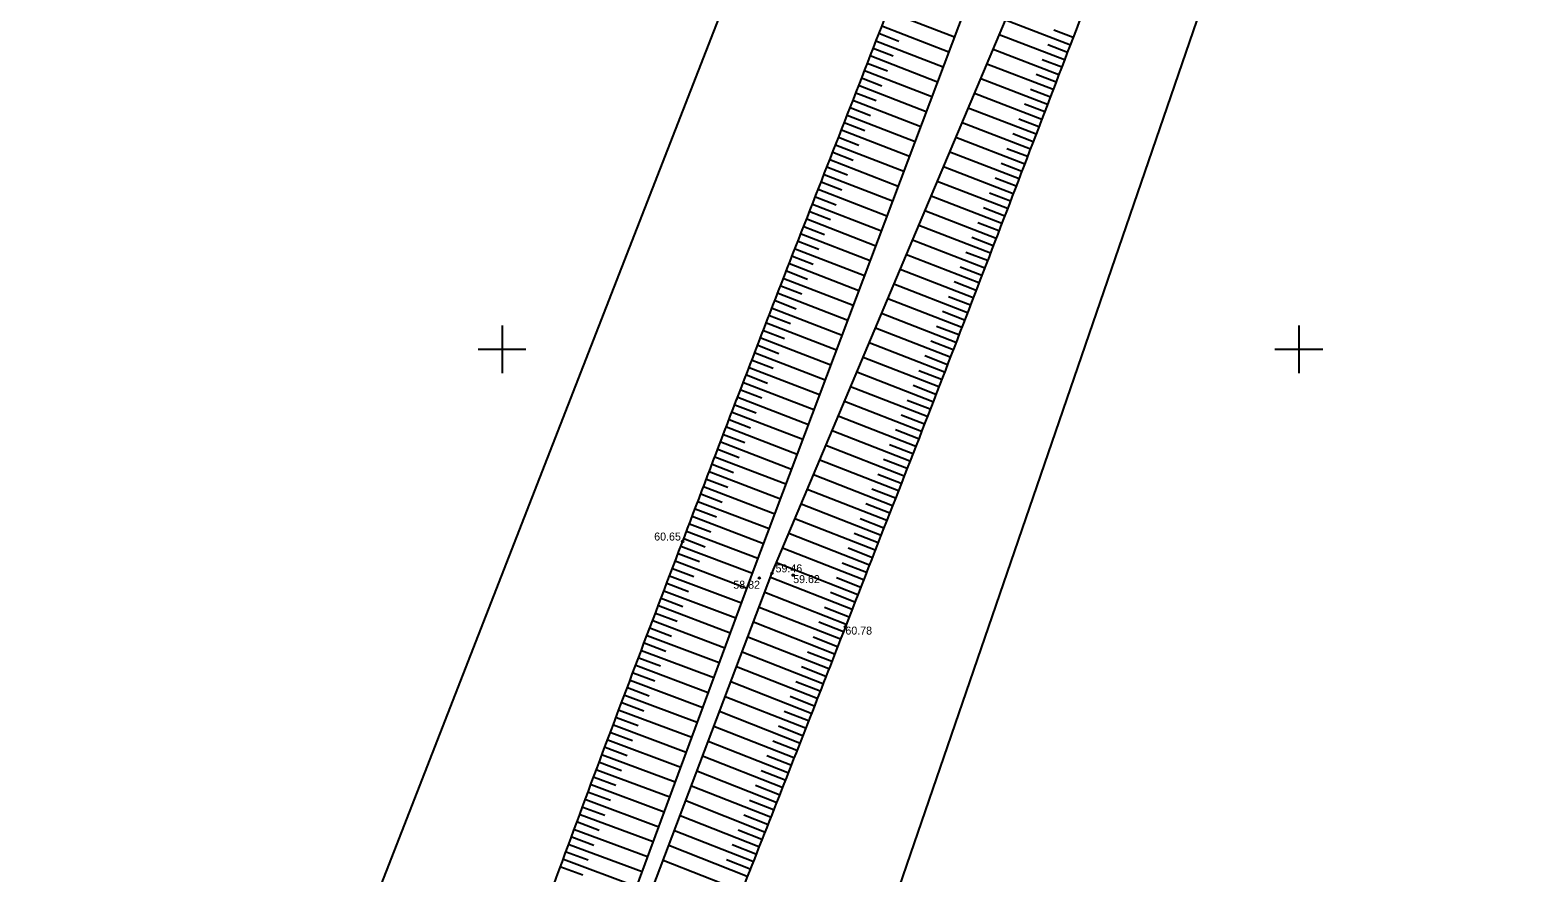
# Model space of a CAD drawing. Extents: x 616607 to 617499, y 408385 to 409695.
# Drawn here: x 617070.4 to 617165, y 408817.1 to 408870 of the extents above; entities that cross this region are included whole.
import ezdxf

# ---------------------------------------------------------------- set-up
doc = ezdxf.new("R2010")
doc.units = 0
for name, color, linetype in [('GEOD_ELEM_####_####_#', 7, 'Continuous'), ('HIDG_GRAV_####_####_#', 7, 'Continuous'), ('RAMI_UZMR_####_####_#', 7, 'Continuous'), ('RELJ_AATZ_####_TKST_#', 7, 'Continuous'), ('RELJ_ELEM_####_####_#', 7, 'Continuous'), ('RELJ_NOGA_####_####_#', 7, 'Continuous')]:
    doc.layers.add(name, color=color, linetype=linetype)

# ---------------------------------------------------------------- blocks, each defined once
blk = doc.blocks.new('PKT')
at = {"layer": 'RELJ_ELEM_####_####_#'}
blk.add_circle((0, 0), 0.05, dxfattribs=at)
blk = doc.blocks.new('KRUSTS')
at = {"layer": 'GEOD_ELEM_####_####_#'}
for p, q in [((0, 1.5), (0, 0)), ((-1.5, 0), (0, 0)), ((0, 0), (0, -1.5)), ((0, 0), (1.5, 0))]:
    blk.add_line(p, q, dxfattribs=at)

msp = doc.modelspace()

# ---------------------------------------------------------------- linework, layer by layer
at = {"layer": 'HIDG_GRAV_####_####_#'}
msp.add_lwpolyline([(616957.708, 408604.801), (616964.717, 408618.582), (616997.814, 408672.816), (617082.506, 408751.106), (617088.497, 408760.889), (617116.937, 408835.934), (617137.451, 408884.548), (617152.78, 408924.733), (617163.79, 408955.542), (617160.997, 408956.152), (617115.742, 408836.043), (617088.001, 408760.943), (617081.506, 408751.106), (616997.147, 408673.705), (616963.717, 408618.582), (616956.708, 408604.801)], dxfattribs=at)
at = {"layer": 'RAMI_UZMR_####_####_#'}
for points in [[(617191.828, 409115.62), (617145.545, 408952.8), (617072.809, 408766.141), (616965.332, 408652.076), (616939.432, 408594.661), (616924.839, 408592.467), (616706.433, 408526.081), (616666.426, 408467.691)], [(616666.426, 408467.691), (616675.529, 408457.882), (616687.228, 408463.356), (616723.888, 408465.775), (616753.554, 408507.232), (616948.282, 408568.831), (616981.528, 408608.531), (617014.563, 408672.892), (617101.571, 408748.246), (617213.472, 409074.039)]]:
    msp.add_lwpolyline(points, dxfattribs=at)
at = {"layer": 'RELJ_NOGA_####_####_#'}
for p, q in [((617124.186, 408871.235), (617128.389, 408869.609)), ((617123.825, 408870.303), (617128.036, 408868.672)), ((617135.664, 408869.103), (617131.591, 408870.661)), ((617123.405, 408869.219), (617123.406, 408869.219)), ((617123.464, 408869.37), (617127.684, 408867.736)), ((617123.586, 408869.685), (617123.587, 408869.685)), ((617123.645, 408869.837), (617124.909, 408869.347)), ((617135.306, 408868.169), (617131.203, 408869.741)), ((617135.843, 408869.57), (617134.626, 408870.035)), ((617123.044, 408868.287), (617123.044, 408868.286)), ((617123.103, 408868.438), (617127.33, 408866.798)), ((617123.225, 408868.753), (617123.226, 408868.752)), ((617123.283, 408868.904), (617124.55, 408868.413)), ((617134.949, 408867.235), (617130.814, 408868.819)), ((617135.485, 408868.636), (617134.259, 408869.105)), ((617122.682, 408867.354), (617122.682, 408867.354)), ((617122.741, 408867.506), (617126.978, 408865.862)), ((617122.863, 408867.82), (617122.864, 408867.82)), ((617122.922, 408867.972), (617124.191, 408867.479)), ((617134.591, 408866.301), (617130.425, 408867.897)), ((617135.128, 408867.702), (617133.892, 408868.175)), ((617122.321, 408866.422), (617122.321, 408866.422)), ((617122.379, 408866.573), (617126.625, 408864.926)), ((617122.501, 408866.888), (617122.502, 408866.888)), ((617122.56, 408867.039), (617123.832, 408866.546)), ((617134.233, 408865.367), (617130.036, 408866.976)), ((617134.77, 408866.768), (617133.525, 408867.245)), ((617121.959, 408865.49), (617121.959, 408865.489)), ((617122.018, 408865.641), (617126.272, 408863.991)), ((617122.14, 408865.956), (617122.141, 408865.955)), ((617122.198, 408866.107), (617123.474, 408865.612)), ((617133.875, 408864.434), (617129.647, 408866.055)), ((617134.412, 408865.834), (617133.158, 408866.315)), ((617121.597, 408864.557), (617121.598, 408864.557)), ((617121.656, 408864.709), (617125.92, 408863.055)), ((617121.778, 408865.023), (617121.779, 408865.023)), ((617121.837, 408865.175), (617123.115, 408864.679)), ((617133.517, 408863.5), (617129.259, 408865.134)), ((617134.054, 408864.9), (617132.79, 408865.385)), ((617121.236, 408863.625), (617121.236, 408863.625)), ((617121.294, 408863.776), (617125.567, 408862.119)), ((617121.416, 408864.091), (617121.417, 408864.091)), ((617121.475, 408864.242), (617122.756, 408863.746)), ((617133.158, 408862.566), (617128.87, 408864.212)), ((617133.696, 408863.967), (617132.423, 408864.455)), ((617120.874, 408862.693), (617120.874, 408862.693)), ((617120.933, 408862.844), (617125.215, 408861.183)), ((617121.055, 408863.159), (617121.056, 408863.158)), ((617121.114, 408863.31), (617122.397, 408862.812)), ((617132.8, 408861.633), (617128.481, 408863.291)), ((617132.979, 408862.1), (617131.688, 408862.595)), ((617133.338, 408863.033), (617132.056, 408863.525)), ((617120.512, 408861.76), (617120.513, 408861.76)), ((617120.571, 408861.912), (617124.862, 408860.247)), ((617120.693, 408862.226), (617120.694, 408862.226)), ((617120.752, 408862.378), (617122.038, 408861.879)), ((617132.442, 408860.699), (617128.092, 408862.37)), ((617132.621, 408861.166), (617131.321, 408861.665)), ((617120.151, 408860.828), (617120.151, 408860.828)), ((617120.209, 408860.979), (617124.509, 408859.311)), ((617120.332, 408861.294), (617120.332, 408861.294)), ((617120.39, 408861.446), (617121.679, 408860.946)), ((617132.083, 408859.766), (617127.704, 408861.449)), ((617132.262, 408860.233), (617130.953, 408860.736)), ((617119.789, 408859.896), (617119.789, 408859.896)), ((617119.848, 408860.047), (617124.157, 408858.376)), ((617119.97, 408860.362), (617119.971, 408860.361)), ((617120.029, 408860.513), (617121.32, 408860.012)), ((617131.724, 408858.832), (617127.315, 408860.527)), ((617131.903, 408859.299), (617130.585, 408859.806)), ((617119.427, 408858.963), (617119.428, 408858.963)), ((617119.486, 408859.115), (617123.804, 408857.44)), ((617119.608, 408859.43), (617119.609, 408859.429)), ((617119.667, 408859.581), (617120.961, 408859.079)), ((617131.365, 408857.899), (617126.927, 408859.607)), ((617131.545, 408858.366), (617130.217, 408858.876)), ((617119.066, 408858.031), (617119.066, 408858.031)), ((617119.124, 408858.182), (617123.452, 408856.504)), ((617119.247, 408858.497), (617119.248, 408858.497)), ((617119.305, 408858.649), (617120.602, 408858.146)), ((617131.006, 408856.966), (617126.538, 408858.686)), ((617131.185, 408857.432), (617129.849, 408857.946)), ((617118.704, 408857.099), (617118.704, 408857.099)), ((617118.763, 408857.25), (617123.099, 408855.568)), ((617118.885, 408857.565), (617118.886, 408857.565)), ((617118.944, 408857.716), (617120.243, 408857.212)), ((617130.647, 408856.033), (617126.149, 408857.764)), ((617130.826, 408856.499), (617129.481, 408857.017)), ((617118.342, 408856.166), (617118.343, 408856.166)), ((617118.401, 408856.318), (617122.746, 408854.632)), ((617118.523, 408856.633), (617118.524, 408856.632)), ((617118.582, 408856.784), (617119.884, 408856.279)), ((617130.287, 408855.099), (617125.761, 408856.844)), ((617130.467, 408855.566), (617129.113, 408856.087)), ((617117.981, 408855.234), (617117.981, 408855.234)), ((617118.04, 408855.385), (617122.395, 408853.699)), ((617118.162, 408855.7), (617118.163, 408855.7)), ((617118.22, 408855.852), (617119.525, 408855.345)), ((617129.927, 408854.166), (617125.372, 408855.922)), ((617130.107, 408854.633), (617128.745, 408855.158)), ((617117.62, 408854.302), (617117.62, 408854.301)), ((617117.679, 408854.453), (617122.042, 408852.763)), ((617117.801, 408854.768), (617117.801, 408854.767)), ((617117.859, 408854.919), (617119.167, 408854.413)), ((617129.208, 408852.3), (617124.595, 408854.08)), ((617129.568, 408853.233), (617124.983, 408855.002)), ((617129.748, 408853.7), (617128.377, 408854.229)), ((617117.259, 408853.369), (617117.259, 408853.369)), ((617117.318, 408853.52), (617121.69, 408851.829)), ((617117.439, 408853.835), (617117.44, 408853.835)), ((617117.498, 408853.987), (617118.808, 408853.479)), ((617128.848, 408851.367), (617124.206, 408853.159)), ((617129.388, 408852.767), (617128.008, 408853.299)), ((617116.898, 408852.436), (617116.898, 408852.436)), ((617116.957, 408852.588), (617121.338, 408850.893)), ((617117.079, 408852.903), (617117.079, 408852.902)), ((617117.137, 408853.054), (617118.45, 408852.546)), ((617128.487, 408850.435), (617123.818, 408852.239)), ((617129.028, 408851.834), (617127.639, 408852.37)), ((617116.538, 408851.504), (617116.538, 408851.503)), ((617116.596, 408851.655), (617120.986, 408849.959)), ((617116.718, 408851.97), (617116.719, 408851.97)), ((617116.776, 408852.121), (617118.092, 408851.612)), ((617128.127, 408849.502), (617123.429, 408851.318)), ((617128.667, 408850.901), (617127.271, 408851.441)), ((617116.177, 408850.571), (617116.178, 408850.571)), ((617116.236, 408850.722), (617120.633, 408849.023)), ((617116.357, 408851.037), (617116.358, 408851.037)), ((617116.416, 408851.189), (617117.734, 408850.679)), ((617127.766, 408848.569), (617123.041, 408850.398)), ((617128.307, 408849.968), (617126.902, 408850.511)), ((617115.817, 408849.638), (617115.817, 408849.638)), ((617115.876, 408849.789), (617120.282, 408848.09)), ((617115.997, 408850.104), (617115.998, 408850.104)), ((617116.056, 408850.256), (617117.376, 408849.746)), ((617127.405, 408847.637), (617122.652, 408849.476)), ((617127.946, 408849.036), (617126.533, 408849.582)), ((617115.336, 408848.39), (617116.661, 408847.879)), ((617115.457, 408848.705), (617115.458, 408848.705)), ((617115.516, 408848.856), (617119.929, 408847.154)), ((617115.637, 408849.171), (617115.638, 408849.171)), ((617115.696, 408849.323), (617117.019, 408848.813)), ((617127.044, 408846.704), (617122.264, 408848.557)), ((617127.585, 408848.103), (617126.164, 408848.653)), ((617114.976, 408847.457), (617116.304, 408846.946)), ((617115.098, 408847.772), (617115.098, 408847.772)), ((617115.156, 408847.923), (617119.576, 408846.219)), ((617115.277, 408848.238), (617115.278, 408848.238)), ((617126.682, 408845.772), (617121.875, 408847.635)), ((617127.224, 408847.17), (617125.794, 408847.724)), ((617114.617, 408846.523), (617115.947, 408846.012)), ((617114.738, 408846.839), (617114.739, 408846.838)), ((617114.797, 408846.99), (617119.225, 408845.285)), ((617114.918, 408847.305), (617114.919, 408847.305)), ((617126.321, 408844.839), (617121.487, 408846.715)), ((617126.863, 408846.238), (617125.425, 408846.795)), ((617114.258, 408845.59), (617115.59, 408845.079)), ((617114.379, 408845.905), (617114.38, 408845.905)), ((617114.438, 408846.057), (617118.873, 408844.351)), ((617114.559, 408846.372), (617114.56, 408846.372)), ((617125.959, 408843.907), (617121.098, 408845.794)), ((617126.502, 408845.305), (617125.055, 408845.866)), ((617113.9, 408844.656), (617115.233, 408844.144)), ((617114.021, 408844.972), (617114.021, 408844.972)), ((617114.079, 408845.123), (617118.521, 408843.418)), ((617114.2, 408845.438), (617114.201, 408845.438)), ((617125.597, 408842.975), (617120.709, 408844.874)), ((617126.14, 408844.373), (617124.686, 408844.938)), ((617113.542, 408843.723), (617114.877, 408843.211)), ((617113.663, 408844.038), (617113.663, 408844.038)), ((617113.721, 408844.19), (617118.169, 408842.484)), ((617113.842, 408844.505), (617113.842, 408844.505)), ((617125.235, 408842.043), (617120.321, 408843.954)), ((617125.778, 408843.441), (617124.316, 408844.009)), ((617113.184, 408842.789), (617114.521, 408842.277)), ((617113.305, 408843.104), (617113.305, 408843.104)), ((617113.363, 408843.256), (617117.817, 408841.548)), ((617113.484, 408843.571), (617113.484, 408843.571)), ((617124.873, 408841.111), (617119.932, 408843.032)), ((617125.416, 408842.509), (617123.946, 408843.08)), ((617112.827, 408841.855), (617114.166, 408841.343)), ((617112.947, 408842.17), (617112.947, 408842.17)), ((617113.005, 408842.322), (617117.465, 408840.615)), ((617113.126, 408842.637), (617113.127, 408842.637)), ((617124.51, 408840.179), (617119.544, 408842.112)), ((617125.054, 408841.577), (617123.576, 408842.151)), ((617112.47, 408840.921), (617113.81, 408840.409)), ((617112.59, 408841.236), (617112.59, 408841.236)), ((617112.648, 408841.388), (617117.114, 408839.682)), ((617112.769, 408841.703), (617112.77, 408841.703)), ((617124.147, 408839.247), (617119.155, 408841.191)), ((617124.691, 408840.645), (617123.206, 408841.223)), ((617112.113, 408839.986), (617113.455, 408839.475)), ((617112.234, 408840.302), (617112.234, 408840.302)), ((617112.291, 408840.454), (617116.762, 408838.749)), ((617112.412, 408840.769), (617112.413, 408840.769)), ((617123.784, 408838.315), (617118.767, 408840.271)), ((617124.328, 408839.713), (617122.835, 408840.294)), ((617111.757, 408839.052), (617113.1, 408838.541)), ((617111.877, 408839.368), (617111.878, 408839.368)), ((617111.935, 408839.519), (617116.41, 408837.813)), ((617112.055, 408839.835), (617112.056, 408839.834)), ((617123.421, 408837.384), (617118.379, 408839.35)), ((617123.966, 408838.781), (617122.464, 408839.366)), ((617111.402, 408838.117), (617112.746, 408837.606)), ((617111.522, 408838.433), (617111.522, 408838.433)), ((617111.579, 408838.585), (617116.058, 408836.881)), ((617111.7, 408838.9), (617111.7, 408838.9)), ((617123.057, 408836.452), (617117.99, 408838.43)), ((617123.602, 408837.849), (617122.093, 408838.438)), ((617111.047, 408837.182), (617112.393, 408836.672)), ((617111.167, 408837.498), (617111.167, 408837.498)), ((617111.224, 408837.65), (617115.708, 408835.949)), ((617111.344, 408837.966), (617111.345, 408837.965)), ((617122.693, 408835.521), (617117.602, 408837.511)), ((617123.239, 408836.918), (617121.723, 408837.51)), ((617110.635, 408836.096), (617110.636, 408836.095)), ((617110.692, 408836.247), (617112.041, 408835.737)), ((617110.812, 408836.563), (617110.812, 408836.563)), ((617110.869, 408836.715), (617115.361, 408835.011)), ((617110.989, 408837.031), (617110.99, 408837.03)), ((617122.329, 408834.589), (617117.214, 408836.589)), ((617122.875, 408835.986), (617121.352, 408836.582)), ((617110.281, 408835.16), (617110.282, 408835.16)), ((617110.338, 408835.312), (617111.69, 408834.801)), ((617110.458, 408835.628), (617110.458, 408835.628)), ((617110.515, 408835.78), (617115.016, 408834.076)), ((617121.964, 408833.658), (617116.836, 408835.666)), ((617122.511, 408835.055), (617120.98, 408835.653)), ((617109.927, 408834.225), (617109.928, 408834.225)), ((617109.985, 408834.377), (617111.338, 408833.865)), ((617110.104, 408834.693), (617110.104, 408834.693)), ((617110.161, 408834.845), (617114.67, 408833.141)), ((617121.6, 408832.727), (617116.481, 408834.731)), ((617122.147, 408834.124), (617120.609, 408834.726)), ((617109.574, 408833.289), (617109.575, 408833.289)), ((617109.631, 408833.441), (617110.987, 408832.93)), ((617109.751, 408833.757), (617109.751, 408833.757)), ((617109.808, 408833.909), (617114.325, 408832.206)), ((617121.235, 408831.796), (617116.128, 408833.799)), ((617121.782, 408833.192), (617120.245, 408833.794)), ((617109.221, 408832.354), (617109.222, 408832.353)), ((617109.279, 408832.506), (617110.637, 408831.994)), ((617109.398, 408832.821), (617109.398, 408832.821)), ((617109.455, 408832.973), (617113.978, 408831.268)), ((617120.87, 408830.865), (617115.773, 408832.863)), ((617121.417, 408832.261), (617119.884, 408832.863)), ((617108.869, 408831.418), (617108.87, 408831.417)), ((617108.926, 408831.57), (617110.287, 408831.058)), ((617109.045, 408831.886), (617109.046, 408831.886)), ((617109.103, 408832.038), (617113.633, 408830.333)), ((617120.504, 408829.934), (617115.42, 408831.93)), ((617121.052, 408831.33), (617119.522, 408831.931)), ((617108.517, 408830.482), (617108.518, 408830.481)), ((617108.574, 408830.634), (617109.936, 408830.122)), ((617108.693, 408830.95), (617108.694, 408830.95)), ((617108.75, 408831.102), (617113.287, 408829.395)), ((617120.139, 408829.003), (617115.065, 408830.995)), ((617120.687, 408830.399), (617119.16, 408830.998)), ((617108.166, 408829.545), (617108.167, 408829.545)), ((617108.223, 408829.697), (617109.587, 408829.186)), ((617108.342, 408830.014), (617108.342, 408830.013)), ((617108.399, 408830.166), (617112.941, 408828.46)), ((617119.773, 408828.072), (617114.711, 408830.06)), ((617120.322, 408829.469), (617118.798, 408830.067)), ((617107.815, 408828.609), (617107.816, 408828.609)), ((617107.872, 408828.761), (617109.237, 408828.249)), ((617107.99, 408829.077), (617107.991, 408829.077)), ((617108.047, 408829.229), (617112.595, 408827.524)), ((617119.408, 408827.142), (617114.357, 408829.127)), ((617119.956, 408828.538), (617118.436, 408829.135)), ((617107.464, 408827.673), (617107.465, 408827.672)), ((617107.521, 408827.825), (617108.888, 408827.313)), ((617107.64, 408828.141), (617107.64, 408828.141)), ((617107.696, 408828.293), (617112.25, 408826.588)), ((617119.042, 408826.211), (617114.003, 408828.192)), ((617119.591, 408827.607), (617118.074, 408828.203)), ((617107.114, 408826.736), (617107.115, 408826.736)), ((617107.171, 408826.888), (617108.539, 408826.377)), ((617107.289, 408827.204), (617107.289, 408827.204)), ((617107.346, 408827.356), (617111.903, 408825.65)), ((617118.676, 408825.28), (617113.649, 408827.258)), ((617119.225, 408826.676), (617117.711, 408827.271)), ((617106.764, 408825.799), (617106.765, 408825.799)), ((617106.821, 408825.951), (617108.19, 408825.44)), ((617106.939, 408826.268), (617106.939, 408826.267)), ((617106.996, 408826.42), (617111.558, 408824.715)), ((617118.31, 408824.35), (617113.295, 408826.323)), ((617118.859, 408825.746), (617117.349, 408826.34)), ((617106.414, 408824.862), (617106.415, 408824.862)), ((617106.471, 408825.014), (617107.841, 408824.503)), ((617106.589, 408825.331), (617106.589, 408825.331)), ((617106.646, 408825.483), (617111.212, 408823.779)), ((617117.944, 408823.419), (617112.941, 408825.389)), ((617118.493, 408824.815), (617116.987, 408825.408)), ((617106.065, 408823.925), (617106.066, 408823.925)), ((617106.121, 408824.077), (617107.493, 408823.566)), ((617106.239, 408824.394), (617106.24, 408824.394)), ((617106.296, 408824.546), (617110.866, 408822.841)), ((617117.577, 408822.489), (617112.587, 408824.454)), ((617118.127, 408823.884), (617116.624, 408824.476)), ((617105.716, 408822.988), (617105.717, 408822.988)), ((617105.772, 408823.14), (617107.145, 408822.629)), ((617105.89, 408823.457), (617105.89, 408823.457)), ((617105.947, 408823.609), (617110.52, 408821.906)), ((617117.211, 408821.558), (617112.232, 408823.519)), ((617117.76, 408822.954), (617116.261, 408823.544)), ((617105.367, 408822.051), (617105.368, 408822.051)), ((617105.423, 408822.203), (617106.797, 408821.692)), ((617105.541, 408822.52), (617105.542, 408822.52)), ((617105.598, 408822.672), (617110.174, 408820.968)), ((617116.844, 408820.628), (617111.878, 408822.584)), ((617117.394, 408822.024), (617115.899, 408822.612)), ((617105.018, 408821.114), (617105.019, 408821.113)), ((617105.075, 408821.266), (617106.449, 408820.755)), ((617105.193, 408821.582), (617105.193, 408821.582)), ((617105.249, 408821.735), (617109.828, 408820.033)), ((617116.478, 408819.697), (617111.524, 408821.65)), ((617117.028, 408821.093), (617115.536, 408821.681)), ((617104.67, 408820.176), (617104.671, 408820.176)), ((617104.727, 408820.329), (617106.101, 408819.818)), ((617104.844, 408820.645), (617104.844, 408820.645)), ((617104.901, 408820.797), (617109.482, 408819.095)), ((617116.111, 408818.767), (617111.169, 408820.715)), ((617116.661, 408820.163), (617115.173, 408820.749)), ((617104.322, 408819.239), (617104.323, 408819.239)), ((617104.378, 408819.391), (617105.754, 408818.881)), ((617104.496, 408819.708), (617104.496, 408819.708)), ((617104.552, 408819.86), (617109.135, 408818.157)), ((617115.744, 408817.837), (617110.815, 408819.78)), ((617116.294, 408819.232), (617114.81, 408819.817)), ((617103.974, 408818.301), (617103.975, 408818.301)), ((617104.03, 408818.454), (617105.406, 408817.943)), ((617104.148, 408818.77), (617104.148, 408818.77)), ((617104.204, 408818.922), (617108.79, 408817.221)), ((617115.378, 408816.906), (617110.461, 408818.846)), ((617115.928, 408818.302), (617114.447, 408818.886)), ((617103.626, 408817.364), (617103.627, 408817.363)), ((617103.683, 408817.516), (617105.059, 408817.006)), ((617103.8, 408817.833), (617103.8, 408817.832)), ((617103.857, 408817.985), (617108.444, 408816.284)), ((617115.011, 408815.976), (617110.107, 408817.911)), ((617115.561, 408817.372), (617114.084, 408817.954))]:
    msp.add_line(p, q, dxfattribs=at)
for points in [[(616952.11, 408607.531), (616956.151, 408614.166), (616960.13, 408620.838), (616964.128, 408627.499), (616969.357, 408636.209), (616974.533, 408644.951), (616979.755, 408653.666), (616982.367, 408658.027), (616985.018, 408662.364), (616987.709, 408666.677), (616989.056, 408668.838), (616990.438, 408670.976), (616991.835, 408673.105), (616992.534, 408674.172), (616993.243, 408675.231), (616993.95, 408676.293), (616994.657, 408677.356), (616995.377, 408678.409), (616996.104, 408679.46), (616998.164, 408682.436), (617000.493, 408685.215), (617003.037, 408687.806), (617005.59, 408690.406), (617008.236, 408692.879), (617011.016, 408695.214), (617013.812, 408697.562), (617016.632, 408699.88), (617019.423, 408702.233), (617020.817, 408703.408), (617022.221, 408704.57), (617023.595, 408705.77), (617024.962, 408706.965), (617026.3, 408708.194), (617027.642, 408709.417), (617031.797, 408713.202), (617035.92, 408717.024), (617040.083, 408720.8), (617044.243, 408724.572), (617048.471, 408728.267), (617052.642, 408732.025), (617056.824, 408735.794), (617060.981, 408739.59), (617065.093, 408743.436), (617067.159, 408745.369), (617069.191, 408747.335), (617071.208, 408749.318), (617072.22, 408750.314), (617073.221, 408751.32), (617074.226, 408752.322), (617075.234, 408753.328), (617076.23, 408754.338), (617077.212, 408755.375), (617081.698, 408760.112), (617084.989, 408765.985), (617087.243, 408772.093), (617089.541, 408778.321), (617091.528, 408784.634), (617093.829, 408790.846), (617099.646, 408806.547), (617105.384, 408822.279), (617111.331, 408837.932), (617116.967, 408852.766), (617122.795, 408867.526), (617128.465, 408882.346), (617134.52, 408898.17), (617140.109, 408914.165), (617146.15, 408930), (617147.203, 408932.762), (617148.413, 408935.46), (617149.608, 408938.162), (617150.805, 408940.87), (617152.218, 408943.437), (617153.491, 408946.151), (617155.134, 408949.654), (617156.252, 408953.338), (617157.386, 408956.937), (617157.388, 408956.942), (617157.376, 408956.956), (617157.382, 408956.955), (617158.587, 408956.687), (617159.792, 408956.42), (617160.997, 408956.152)], [(617163.79, 408955.542), (617165.45, 408955.194), (617167.11, 408954.846), (617168.77, 408954.498), (617168.913, 408954.468), (617169.034, 408954.324), (617169.074, 408954.183), (617169.128, 408953.99), (617169.08, 408953.773), (617169.007, 408953.587), (617168.835, 408953.148), (617168.665, 408952.708), (617168.483, 408952.272), (617167.485, 408949.894), (617166.495, 408947.512), (617165.486, 408945.138), (617164.477, 408942.762), (617163.444, 408940.395), (617162.435, 408938.019), (617160.416, 408933.265), (617158.392, 408928.513), (617156.542, 408923.692), (617150.713, 408908.507), (617144.931, 408893.305), (617139.111, 408878.118), (617136.201, 408870.523), (617133.294, 408862.928), (617130.378, 408855.336), (617127.463, 408847.744), (617124.504, 408840.168), (617121.547, 408832.592), (617116.624, 408819.98), (617111.621, 408807.399), (617106.663, 408794.801), (617101.918, 408782.741), (617097.386, 408770.604), (617092.68, 408758.522), (617091.748, 408756.128), (617090.638, 408753.8), (617089.099, 408751.701), (617087.891, 408750.055), (617086.512, 408748.607), (617085.075, 408747.191), (617082.094, 408744.254), (617079.138, 408741.303), (617076.078, 408738.453), (617073.02, 408735.605), (617069.97, 408732.751), (617066.861, 408729.96), (617060.644, 408724.38), (617054.349, 408718.89), (617048.124, 408713.32), (617041.902, 408707.753), (617035.717, 408702.149), (617029.576, 408696.491), (617026.506, 408693.662), (617023.563, 408690.704), (617020.596, 408687.763), (617017.626, 408684.818), (617014.683, 408681.855), (617011.931, 408678.697), (617008.517, 408674.776), (617005.359, 408670.661), (617002.288, 408666.476), (616999.318, 408662.428), (616996.36, 408658.374), (616993.424, 408654.302), (616990.492, 408650.235), (616987.575, 408646.161), (616984.691, 408642.059), (616983.288, 408640.063), (616981.951, 408638.02), (616980.703, 408635.922), (616979.453, 408633.819), (616978.237, 408631.7), (616977.033, 408629.572), (616975.83, 408627.444), (616974.65, 408625.305), (616973.452, 408623.174), (616972.259, 408621.052), (616970.984, 408618.974), (616969.729, 408616.893), (616969.613, 408616.701), (616969.41, 408616.592), (616969.29, 408616.383), (616968.995, 408615.872), (616968.948, 408615.291), (616969.02, 408614.761), (616969.09, 408614.251), (616969.19, 408613.683), (616969.493, 408613.251)]]:
    msp.add_open_spline(points, degree=3, dxfattribs=at)

# ---------------------------------------------------------------- block references
at = {"layer": 'GEOD_ELEM_####_####_#'}
for p in [(617100, 408850), (617150, 408850)]:
    msp.add_blockref('KRUSTS', p, dxfattribs=at)
at = {"layer": 'RELJ_ELEM_####_####_#'}
for p in [(617111.331, 408837.932), (617116.148, 408835.648), (617116.937, 408835.934), (617118.27, 408835.823), (617121.547, 408832.592)]:
    msp.add_blockref('PKT', p, dxfattribs=at)

# ---------------------------------------------------------------- texts
at = {"layer": 'RELJ_AATZ_####_TKST_#'}
for s, p in [('60.65', (617109.548, 408837.996)), ('59.46', (617117.162, 408835.999)), ('58.82', (617114.512, 408834.971)), ('59.62', (617118.27, 408835.323)), ('60.78', (617121.547, 408832.092))]:
    msp.add_text(s, height=0.5, dxfattribs=at).set_placement(p)

doc.saveas('drawing.dxf')
